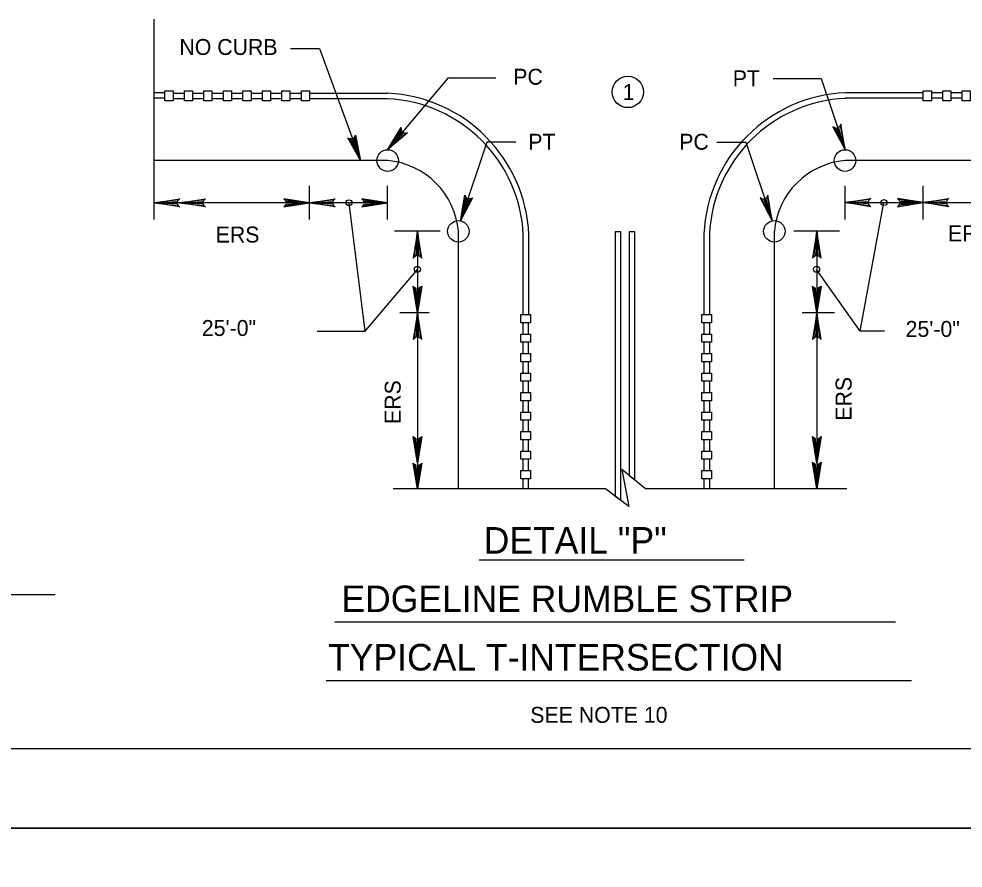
# Model space of a CAD drawing. Extents: x 632008 to 634206, y 294231 to 297795.
# Drawn here: x 632427 to 632604.8, y 296005.1 to 296165 of the extents above; entities that cross this region are included whole.
import ezdxf

# ---------------------------------------------------------------- set-up
doc = ezdxf.new("R2010")
doc.units = 0
for name, color, linetype in [('1', 7, 'Continuous'), ('3', 7, 'Continuous'), ('Level 2', 7, 'Continuous'), ('PLT-BNDY', 7, 'Continuous')]:
    doc.layers.add(name, color=color, linetype=linetype)

msp = doc.modelspace()

# ---------------------------------------------------------------- linework, layer by layer
at = {"layer": '1'}
for p, q in [((632513.68, 296063.15), (632563.56, 296063.15)), ((632244.66, 296056.61), (632433.76, 296056.61)), ((632486.5, 296051.47), (632592.09, 296051.47)), ((632484.85, 296040.47), (632595.08, 296040.47))]:
    msp.add_line(p, q, dxfattribs=at)
msp.add_lwpolyline([(632833.86, 296027.62), (632833.86, 296591.62), (632047.86, 296591.62), (632047.86, 296027.62), (632833.86, 296027.62), (632833.86, 296053.98), (632633.86, 296053.98), (632633.86, 296118.66), (632833.86, 296118.66), (632833.86, 296147.62), (632633.86, 296147.62), (632633.86, 296027.62), (632712.66, 296027.62), (632712.66, 296053.98), (632712.66, 296027.62), (632789.66, 296027.62), (632789.66, 296053.98), (632789.66, 296041.66), (632833.86, 296041.66)], dxfattribs=at)
for points in [[(632540.32, 296074.36), (632540.32, 296124.92), (632539.27, 296124.92), (632539.27, 296075.14)], [(632542.96, 296078.19), (632542.96, 296124.92), (632541.91, 296124.92), (632541.91, 296079.05)]]:
    msp.add_lwpolyline(points, close=True, dxfattribs=at)
at = {"layer": '3'}
for points in [[(632520.56, 296141.76), (632515.09, 296141.76), (632510.13, 296126.99)], [(632558.44, 296141.76), (632563.91, 296141.76), (632568.88, 296126.99)], [(632512.14, 296131.17), (632511.77, 296131.12), (632510.13, 296126.99), (632512.14, 296131.17), (632512.41, 296131.33), (632510.13, 296126.99), (632511.33, 296131.26), (632511.07, 296131.52), (632510.13, 296126.99), (632510.94, 296131.82), (632511.07, 296131.52)], [(632566.86, 296131.17), (632567.23, 296131.12), (632568.88, 296126.99), (632566.86, 296131.17), (632566.6, 296131.33), (632568.88, 296126.99), (632567.67, 296131.26), (632567.93, 296131.52), (632568.88, 296126.99), (632568.06, 296131.82), (632567.93, 296131.52)]]:
    msp.add_lwpolyline(points, dxfattribs=at)
for centre, radius in [((632541.67, 296151.23), 2.95), ((632509.74, 296125), 2.03), ((632569.27, 296125), 2.03)]:
    msp.add_circle(centre, radius, dxfattribs=at)
at = {"layer": 'Level 2'}
for p, q in [((632452.42, 296127.2), (632452.42, 296164.91)), ((632454.46, 296151.06), (632452.42, 296151.06)), ((632458.13, 296150.97), (632455.99, 296150.97)), ((632461.8, 296150.97), (632459.66, 296150.97)), ((632465.48, 296150.97), (632463.33, 296150.97)), ((632469.15, 296150.97), (632467.01, 296150.97)), ((632472.82, 296150.97), (632470.68, 296150.97)), ((632476.49, 296150.97), (632474.35, 296150.97)), ((632480.17, 296150.97), (632478.02, 296150.97)), ((632496.42, 296150.97), (632481.7, 296150.97)), ((632597.31, 296151.06), (632582.6, 296151.06)), ((632600.98, 296151.06), (632598.84, 296151.06)), ((632604.65, 296151.06), (632602.51, 296151.06)), ((632454.46, 296150.04), (632452.42, 296150.04)), ((632458.13, 296149.95), (632455.99, 296149.95)), ((632461.8, 296149.95), (632459.66, 296149.95)), ((632465.48, 296149.95), (632463.33, 296149.95)), ((632469.15, 296149.95), (632467.01, 296149.95)), ((632472.82, 296149.95), (632470.68, 296149.95)), ((632476.49, 296149.95), (632474.35, 296149.95)), ((632480.17, 296149.95), (632478.02, 296149.95)), ((632496.42, 296149.95), (632481.7, 296149.95)), ((632597.31, 296150.05), (632582.6, 296150.05)), ((632600.98, 296150.05), (632598.84, 296150.05)), ((632604.65, 296150.05), (632602.51, 296150.05)), ((632496.42, 296138.32), (632452.56, 296138.32)), ((632626.45, 296138.32), (632582.58, 296138.32)), ((632481.7, 296127.2), (632481.7, 296133.55)), ((632496.42, 296127.2), (632496.42, 296133.55)), ((632582.58, 296127.24), (632582.58, 296133.59)), ((632597.31, 296127.24), (632597.31, 296133.59)), ((632496.42, 296130.38), (632452.42, 296130.38)), ((632582.58, 296130.42), (632626.45, 296130.42)), ((632506.32, 296125), (632497.72, 296125)), ((632502.02, 296125), (632502.02, 296076.52)), ((632509.74, 296076.52), (632509.74, 296125)), ((632521.94, 296109.34), (632521.94, 296124.39)), ((632523, 296109.34), (632523, 296124.39)), ((632556.02, 296109.34), (632556.02, 296124.49)), ((632557.08, 296109.34), (632557.08, 296124.49)), ((632569.27, 296076.52), (632569.27, 296125)), ((632581.56, 296125), (632572.96, 296125)), ((632577.26, 296125), (632577.26, 296076.52)), ((632504.26, 296109.66), (632498.71, 296109.66)), ((632580.57, 296109.66), (632574.5, 296109.66)), ((632521.94, 296105.66), (632521.94, 296107.8)), ((632522.95, 296105.66), (632522.95, 296107.8)), ((632556.06, 296105.66), (632556.06, 296107.8)), ((632557.08, 296105.66), (632557.08, 296107.8)), ((632521.94, 296101.99), (632521.94, 296104.13)), ((632522.95, 296101.99), (632522.95, 296104.13)), ((632556.06, 296101.99), (632556.06, 296104.13)), ((632557.08, 296101.99), (632557.08, 296104.13)), ((632521.94, 296098.32), (632521.94, 296100.46)), ((632522.95, 296098.32), (632522.95, 296100.46)), ((632556.06, 296098.32), (632556.06, 296100.46)), ((632557.08, 296098.32), (632557.08, 296100.46)), ((632521.94, 296094.64), (632521.94, 296096.79)), ((632522.95, 296094.64), (632522.95, 296096.79)), ((632556.06, 296094.64), (632556.06, 296096.79)), ((632557.08, 296094.64), (632557.08, 296096.79)), ((632521.94, 296090.97), (632521.94, 296093.11)), ((632522.95, 296090.97), (632522.95, 296093.11)), ((632556.06, 296090.97), (632556.06, 296093.11)), ((632557.08, 296090.97), (632557.08, 296093.11)), ((632521.94, 296087.3), (632521.94, 296089.44)), ((632522.95, 296087.3), (632522.95, 296089.44)), ((632556.06, 296087.3), (632556.06, 296089.44)), ((632557.08, 296087.3), (632557.08, 296089.44)), ((632521.94, 296083.63), (632521.94, 296085.77)), ((632522.95, 296083.63), (632522.95, 296085.77)), ((632556.06, 296083.63), (632556.06, 296085.77)), ((632557.08, 296083.63), (632557.08, 296085.77)), ((632521.94, 296079.95), (632521.94, 296082.1)), ((632522.95, 296079.95), (632522.95, 296082.1)), ((632556.06, 296079.95), (632556.06, 296082.1)), ((632557.08, 296079.95), (632557.08, 296082.1)), ((632545.02, 296076.52), (632540.52, 296080.17)), ((632540.52, 296080.17), (632541.87, 296073.2)), ((632521.94, 296076.52), (632521.94, 296078.42)), ((632522.95, 296076.52), (632522.95, 296078.42)), ((632556.06, 296076.52), (632556.06, 296078.42)), ((632557.08, 296076.52), (632557.08, 296078.42)), ((632537.44, 296076.52), (632497.49, 296076.52)), ((632541.87, 296073.2), (632537.44, 296076.52)), ((632582.9, 296076.52), (632545.02, 296076.52))]:
    msp.add_line(p, q, dxfattribs=at)
for points in [[(632478.09, 296159.43), (632483.6, 296159.43), (632491.29, 296138.32)], [(632516.79, 296153.8), (632507.75, 296153.8), (632496.42, 296140.34)], [(632569.03, 296153.76), (632578.07, 296153.76), (632582.58, 296140.34)], [(632499.83, 296143.48), (632499.47, 296143.57), (632496.42, 296140.34), (632499.83, 296143.48), (632500.14, 296143.53), (632496.42, 296140.34), (632499.11, 296143.87), (632498.97, 296144.2), (632496.42, 296140.34), (632498.96, 296144.53), (632498.97, 296144.2)], [(632580.57, 296144.52), (632580.94, 296144.47), (632582.58, 296140.34), (632580.57, 296144.52), (632580.3, 296144.68), (632582.58, 296140.34), (632581.38, 296144.61), (632581.64, 296144.87), (632582.58, 296140.34), (632581.77, 296145.17), (632581.64, 296144.87)], [(632490.25, 296142.84), (632490, 296142.57), (632491.29, 296138.32), (632490.25, 296142.84), (632490.36, 296143.13), (632491.29, 296138.32), (632489.56, 296142.4), (632489.2, 296142.44), (632491.29, 296138.32), (632488.91, 296142.6), (632489.2, 296142.44)], [(632457.02, 296129.8), (632456.86, 296130.13), (632452.42, 296130.38), (632457.02, 296129.8), (632457.26, 296129.6), (632452.42, 296130.38), (632456.85, 296130.59), (632457.01, 296130.92), (632452.42, 296130.38), (632457.26, 296131.14), (632457.01, 296130.92)], [(632461.84, 296129.8), (632461.67, 296130.13), (632457.24, 296130.38), (632461.84, 296129.8), (632462.08, 296129.6), (632457.24, 296130.38), (632461.67, 296130.59), (632461.83, 296130.92), (632457.24, 296130.38), (632462.08, 296131.14), (632461.83, 296130.92)], [(632477.09, 296129.8), (632477.26, 296130.13), (632481.7, 296130.38), (632477.09, 296129.8), (632476.86, 296129.6), (632481.7, 296130.38), (632477.27, 296130.59), (632477.11, 296130.92), (632481.7, 296130.38), (632476.86, 296131.14), (632477.11, 296130.92)], [(632486.3, 296129.8), (632486.13, 296130.13), (632481.7, 296130.38), (632486.3, 296129.8), (632486.54, 296129.6), (632481.7, 296130.38), (632486.12, 296130.59), (632486.29, 296130.92), (632481.7, 296130.38), (632486.54, 296131.14), (632486.29, 296130.92)], [(632491.82, 296129.8), (632491.99, 296130.13), (632496.42, 296130.38), (632491.82, 296129.8), (632491.58, 296129.6), (632496.42, 296130.38), (632491.99, 296130.59), (632491.83, 296130.92), (632496.42, 296130.38), (632491.58, 296131.14), (632491.83, 296130.92)], [(632587.18, 296129.84), (632587.02, 296130.17), (632582.58, 296130.42), (632587.18, 296129.84), (632587.42, 296129.64), (632582.58, 296130.42), (632587.01, 296130.63), (632587.17, 296130.96), (632582.58, 296130.42), (632587.42, 296131.18), (632587.17, 296130.96)], [(632592.7, 296129.84), (632592.87, 296130.17), (632597.31, 296130.42), (632592.7, 296129.84), (632592.47, 296129.64), (632597.31, 296130.42), (632592.88, 296130.63), (632592.72, 296130.96), (632597.31, 296130.42), (632592.47, 296131.18), (632592.72, 296130.96)], [(632601.91, 296129.84), (632601.74, 296130.17), (632597.31, 296130.42), (632601.91, 296129.84), (632602.14, 296129.64), (632597.31, 296130.42), (632601.73, 296130.63), (632601.9, 296130.96), (632597.31, 296130.42), (632602.14, 296131.18), (632601.9, 296130.96)], [(632483.17, 296106.18), (632492.21, 296106.18), (632489.15, 296130.38)], [(632590.03, 296106.18), (632585.43, 296106.18), (632589.92, 296130.41)], [(632502.62, 296120.21), (632502.28, 296120.38), (632502.02, 296125), (632502.62, 296120.21), (632502.83, 296119.96), (632502.02, 296125), (632501.79, 296120.39), (632501.45, 296120.22), (632502.02, 296125), (632501.22, 296119.96), (632501.45, 296120.22)], [(632577.86, 296120.21), (632577.52, 296120.38), (632577.26, 296125), (632577.86, 296120.21), (632578.07, 296119.96), (632577.26, 296125), (632577.03, 296120.39), (632576.69, 296120.22), (632577.26, 296125), (632576.46, 296119.96), (632576.69, 296120.22)], [(632483.17, 296106.18), (632492.21, 296106.18), (632502.04, 296117.83)], [(632590.03, 296106.18), (632585.43, 296106.18), (632577.21, 296117.83)], [(632502.62, 296114.46), (632502.28, 296114.28), (632502.02, 296109.66), (632502.62, 296114.46), (632502.83, 296114.7), (632502.02, 296109.66), (632501.79, 296114.28), (632501.45, 296114.44), (632502.02, 296109.66), (632501.22, 296114.7), (632501.45, 296114.44)], [(632577.86, 296114.46), (632577.52, 296114.28), (632577.26, 296109.66), (632577.86, 296114.46), (632578.07, 296114.7), (632577.26, 296109.66), (632577.03, 296114.28), (632576.69, 296114.44), (632577.26, 296109.66), (632576.46, 296114.7), (632576.69, 296114.44)], [(632502.62, 296104.87), (632502.28, 296105.04), (632502.02, 296109.66), (632502.62, 296104.87), (632502.83, 296104.62), (632502.02, 296109.66), (632501.79, 296105.05), (632501.45, 296104.88), (632502.02, 296109.66), (632501.22, 296104.62), (632501.45, 296104.88)], [(632577.86, 296104.87), (632577.52, 296105.04), (632577.26, 296109.66), (632577.86, 296104.87), (632578.07, 296104.62), (632577.26, 296109.66), (632577.03, 296105.05), (632576.69, 296104.88), (632577.26, 296109.66), (632576.46, 296104.62), (632576.69, 296104.88)], [(632502.63, 296086.12), (632502.28, 296085.95), (632502.02, 296081.33), (632502.63, 296086.12), (632502.84, 296086.37), (632502.02, 296081.33), (632501.8, 296085.94), (632501.46, 296086.11), (632502.02, 296081.33), (632501.22, 296086.37), (632501.46, 296086.11)], [(632577.87, 296086.12), (632577.52, 296085.95), (632577.26, 296081.33), (632577.87, 296086.12), (632578.08, 296086.37), (632577.26, 296081.33), (632577.04, 296085.94), (632576.7, 296086.11), (632577.26, 296081.33), (632576.46, 296086.37), (632576.7, 296086.11)], [(632502.63, 296081.11), (632502.28, 296080.95), (632502.02, 296076.52), (632502.63, 296081.11), (632502.84, 296081.35), (632502.02, 296076.52), (632501.8, 296080.94), (632501.46, 296081.1), (632502.02, 296076.52), (632501.22, 296081.35), (632501.46, 296081.1)], [(632577.87, 296081.32), (632577.52, 296081.14), (632577.26, 296076.52), (632577.87, 296081.32), (632578.08, 296081.56), (632577.26, 296076.52), (632577.04, 296081.13), (632576.7, 296081.3), (632577.26, 296076.52), (632576.46, 296081.56), (632576.7, 296081.3)]]:
    msp.add_lwpolyline(points, dxfattribs=at)
for points in [[(632454.46, 296151.43), (632455.99, 296151.43), (632455.99, 296149.59), (632454.46, 296149.59)], [(632458.13, 296151.43), (632459.66, 296151.43), (632459.66, 296149.59), (632458.13, 296149.59)], [(632461.8, 296151.43), (632463.33, 296151.43), (632463.33, 296149.59), (632461.8, 296149.59)], [(632465.48, 296151.43), (632467.01, 296151.43), (632467.01, 296149.59), (632465.48, 296149.59)], [(632469.15, 296151.43), (632470.68, 296151.43), (632470.68, 296149.59), (632469.15, 296149.59)], [(632472.82, 296151.43), (632474.35, 296151.43), (632474.35, 296149.59), (632472.82, 296149.59)], [(632476.49, 296151.43), (632478.02, 296151.43), (632478.02, 296149.59), (632476.49, 296149.59)], [(632480.17, 296151.43), (632481.7, 296151.43), (632481.7, 296149.59), (632480.17, 296149.59)], [(632597.31, 296151.43), (632598.84, 296151.43), (632598.84, 296149.59), (632597.31, 296149.59)], [(632600.98, 296151.43), (632602.51, 296151.43), (632602.51, 296149.59), (632600.98, 296149.59)], [(632604.65, 296151.43), (632606.18, 296151.43), (632606.18, 296149.59), (632604.65, 296149.59)], [(632523.32, 296109.34), (632523.32, 296107.8), (632521.49, 296107.8), (632521.49, 296109.34)], [(632557.45, 296109.34), (632557.45, 296107.8), (632555.61, 296107.8), (632555.61, 296109.34)], [(632523.32, 296105.66), (632523.32, 296104.13), (632521.49, 296104.13), (632521.49, 296105.66)], [(632557.45, 296105.66), (632557.45, 296104.13), (632555.61, 296104.13), (632555.61, 296105.66)], [(632523.32, 296101.99), (632523.32, 296100.46), (632521.49, 296100.46), (632521.49, 296101.99)], [(632557.45, 296101.99), (632557.45, 296100.46), (632555.61, 296100.46), (632555.61, 296101.99)], [(632523.32, 296098.32), (632523.32, 296096.79), (632521.49, 296096.79), (632521.49, 296098.32)], [(632557.45, 296098.32), (632557.45, 296096.79), (632555.61, 296096.79), (632555.61, 296098.32)], [(632523.32, 296094.64), (632523.32, 296093.11), (632521.49, 296093.11), (632521.49, 296094.64)], [(632557.45, 296094.64), (632557.45, 296093.11), (632555.61, 296093.11), (632555.61, 296094.64)], [(632523.32, 296090.97), (632523.32, 296089.44), (632521.49, 296089.44), (632521.49, 296090.97)], [(632557.45, 296090.97), (632557.45, 296089.44), (632555.61, 296089.44), (632555.61, 296090.97)], [(632523.32, 296087.3), (632523.32, 296085.77), (632521.49, 296085.77), (632521.49, 296087.3)], [(632557.45, 296087.3), (632557.45, 296085.77), (632555.61, 296085.77), (632555.61, 296087.3)], [(632523.32, 296083.63), (632523.32, 296082.1), (632521.49, 296082.1), (632521.49, 296083.63)], [(632557.45, 296083.63), (632557.45, 296082.1), (632555.61, 296082.1), (632555.61, 296083.63)], [(632523.32, 296079.95), (632523.32, 296078.42), (632521.49, 296078.42), (632521.49, 296079.95)], [(632557.45, 296079.95), (632557.45, 296078.42), (632555.61, 296078.42), (632555.61, 296079.95)]]:
    msp.add_lwpolyline(points, close=True, dxfattribs=at)
for centre, radius in [((632496.42, 296138.32), 2.03), ((632582.58, 296138.32), 2.03), ((632489.15, 296130.38), 0.558), ((632589.92, 296130.41), 0.558), ((632502.03, 296117.87), 0.581), ((632577.21, 296117.87), 0.581)]:
    msp.add_circle(centre, radius, dxfattribs=at)
for centre, radius, start, end in [((632495.14, 296123.11), 27.91, 2.6354, 87.3646), ((632583.88, 296123.2), 27.91, 92.6354, 177.3646), ((632495.14, 296123.11), 26.86, 2.6354, 87.3646), ((632583.88, 296123.2), 26.86, 92.6354, 177.3646), ((632495.19, 296123.77), 14.6, 4.837, 85.163), ((632583.81, 296123.77), 14.6, 94.837, 175.163)]:
    msp.add_arc(centre, radius, start, end, dxfattribs=at)
at = {"layer": 'PLT-BNDY'}
for points in [[(632007.86, 296606.62), (632848.86, 296606.62), (632848.86, 296012.62), (632007.86, 296012.62)], [(632007.86, 296012.62), (632848.86, 296012.62), (632848.86, 295418.62), (632007.86, 295418.62)]]:
    msp.add_lwpolyline(points, close=True, dxfattribs=at)

# ---------------------------------------------------------------- texts
at = {"layer": '3'}
for s, p in [('PT', (632522.91, 296140.36)), ('PC', (632551.34, 296140.36))]:
    msp.add_text(s, height=3, dxfattribs=at).set_placement(p)
at = {"layer": 'Level 2'}
for s, height, p in [('NO CURB', 3, (632457.19, 296158.2)), ('PC', 3, (632520.08, 296152.6)), ('PT', 3, (632561.43, 296152.3)), ('1', 3, (632540.69, 296149.73)), ('ERS', 3, (632464.02, 296122.89)), ('ERS', 3, (632601.97, 296123.12)), ('25\'-0"', 3, (632461.42, 296105.3)), ('25\'-0"', 3, (632593.99, 296105.12)), ('DETAIL "P"', 5, (632514.52, 296064.32)), ('EDGELINE RUMBLE STRIP', 5, (632487.71, 296053.32)), ('TYPICAL T-INTERSECTION', 5, (632485.21, 296042.32)), ('SEE NOTE 10', 3, (632523.28, 296032.47))]:
    msp.add_text(s, height=height, dxfattribs=at).set_placement(p)
for p in [(632583.81, 296089.34), (632498.87, 296088.72)]:
    msp.add_text('ERS', height=3, rotation=90, dxfattribs=at).set_placement(p)

doc.saveas('drawing.dxf')
